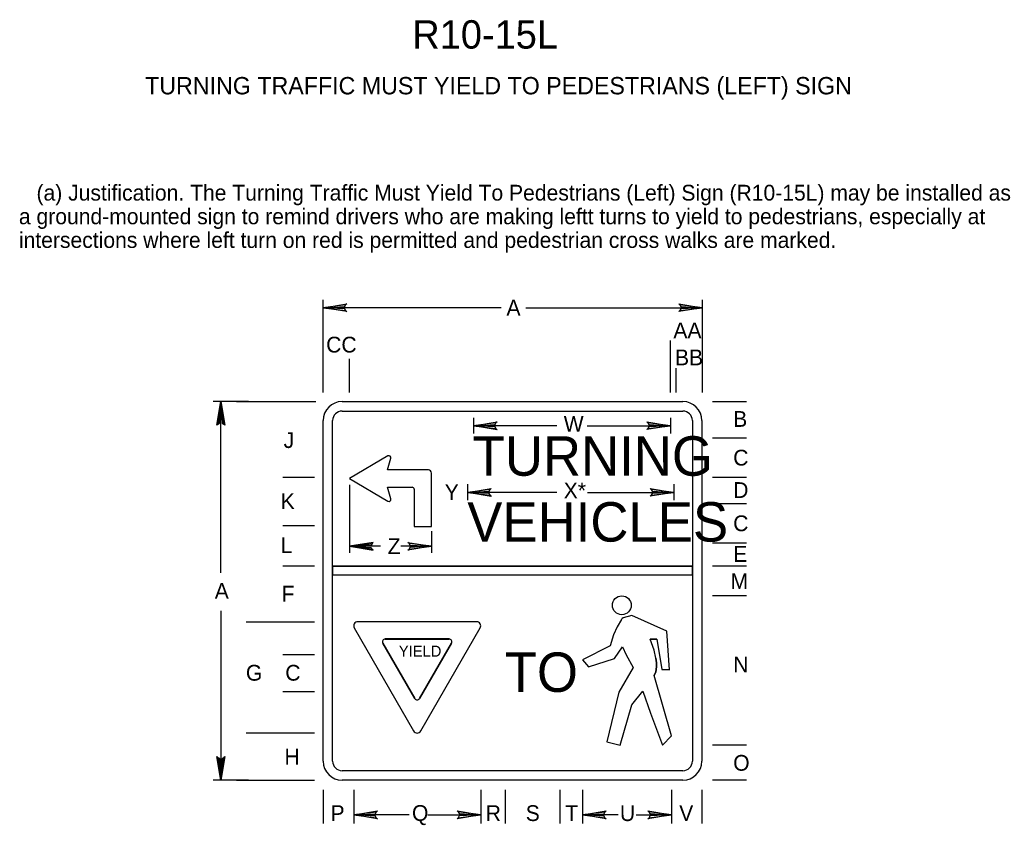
# Model space of a CAD drawing. Extents: x 0.013 to 0.193, y 0.003 to 0.259.
# Drawn here: x 0.0358 to 0.1928, y 0.1316 to 0.2592 of the extents above; entities that cross this region are included whole.
import ezdxf

# ---------------------------------------------------------------- set-up
doc = ezdxf.new("R2010")
doc.units = 0
for name, color, linetype in [('1', 7, 'Continuous'), ('11', 7, 'Continuous'), ('12', 7, 'Continuous'), ('2', 7, 'Continuous'), ('3', 7, 'Continuous')]:
    doc.layers.add(name, color=color, linetype=linetype)

# ---------------------------------------------------------------- blocks, each defined once
blk = doc.blocks.new('RARROW')
at = {"layer": '3'}
for p, q in [((-2.156, 0.28500000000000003), (-2.2665, 0.384625)), ((-2.2665, 0.384625), (0, 0)), ((0, 0), (-2.2665, -0.379125)), ((-2.156, 0.28500000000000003), (-2.075625, 0.12075)), ((0, 0), (-2.156, 0.28500000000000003)), ((-2.14975, -0.2705), (0, 0)), ((-2.075625, 0.12075), (0, 0)), ((0, 0), (-2.074, -0.108)), ((-2.2665, -0.379125), (-2.14975, -0.2705)), ((-2.074, -0.108), (-2.14975, -0.2705))]:
    blk.add_line(p, q, dxfattribs=at)

msp = doc.modelspace()

# ---------------------------------------------------------------- linework, layer by layer
at = {"layer": '11'}
for p, q in [((0.08690494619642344, 0.19868508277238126), (0.14090494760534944, 0.19868508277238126)), ((0.08390494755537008, 0.14168508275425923), (0.08390494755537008, 0.1956850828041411)), ((0.14390494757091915, 0.19568508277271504), (0.1439049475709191, 0.14168508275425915)), ((0.09417475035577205, 0.19007234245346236), (0.08808089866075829, 0.18649377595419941)), ((0.09409819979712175, 0.1878687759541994), (0.09463316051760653, 0.18971593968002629)), ((0.10058089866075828, 0.1878687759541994), (0.09409819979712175, 0.1878687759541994)), ((0.10108089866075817, 0.17886877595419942), (0.10108089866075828, 0.1873687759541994)), ((0.08808089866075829, 0.18649377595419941), (0.094174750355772, 0.18291520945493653)), ((0.09463316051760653, 0.1832716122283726), (0.09409819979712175, 0.1851187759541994)), ((0.09409819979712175, 0.1851187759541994), (0.09801839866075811, 0.1851187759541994)), ((0.09833089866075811, 0.1848062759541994), (0.09833089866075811, 0.17886877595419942)), ((0.09833089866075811, 0.17886877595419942), (0.10108089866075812, 0.17886877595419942)), ((0.14090549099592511, 0.13868508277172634), (0.08690494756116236, 0.13868508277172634))]:
    msp.add_line(p, q, dxfattribs=at)
for centre, radius, start, end in [((0.08690494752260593, 0.1956850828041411), 0.002999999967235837, 90, 180), ((0.14090494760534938, 0.1956850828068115), 0.0029999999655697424, 0, 90), ((0.09433299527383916, 0.18980287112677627), 0.0003125, 343.84835103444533, 120.42325111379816), ((0.10058089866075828, 0.1873687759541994), 0.0005, 1.4210854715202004e-14, 90.00000000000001), ((0.09801839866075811, 0.1848062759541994), 0.0003125, 1.4210854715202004e-14, 90.00000000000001), ((0.09433299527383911, 0.18318468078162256), 0.0003125, 239.57674888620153, 16.151648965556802), ((0.0869049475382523, 0.14168508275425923), 0.0029999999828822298, 180, 270), ((0.14090494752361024, 0.14168508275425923), 0.003000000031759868, 270, 0)]:
    msp.add_arc(centre, radius, start, end, dxfattribs=at)
at = {"layer": '3'}
for p, q in [((0.0839023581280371, 0.20010055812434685), (0.0839023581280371, 0.21482011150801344)), ((0.11208424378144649, 0.21357011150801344), (0.0839023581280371, 0.21357011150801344)), ((0.11600603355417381, 0.21357011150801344), (0.14398465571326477, 0.21357011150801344)), ((0.14398465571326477, 0.20010055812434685), (0.14398465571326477, 0.21482011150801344)), ((0.13893855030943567, 0.20010055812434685), (0.13893855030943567, 0.20838502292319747)), ((0.08808089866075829, 0.20010055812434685), (0.08808089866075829, 0.20547034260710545)), ((0.13985770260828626, 0.20010055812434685), (0.13985770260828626, 0.20395857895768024)), ((0.07208256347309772, 0.19868508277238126), (0.06645704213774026, 0.19868508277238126)), ((0.06707754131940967, 0.19493508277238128), (0.06770704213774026, 0.19868508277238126)), ((0.06770704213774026, 0.19868508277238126), (0.06724059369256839, 0.1951179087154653)), ((0.06750941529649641, 0.19525089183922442), (0.06770704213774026, 0.19868508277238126)), ((0.06770704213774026, 0.19868508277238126), (0.06788380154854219, 0.1952535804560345)), ((0.06814975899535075, 0.19512824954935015), (0.06770704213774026, 0.19868508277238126)), ((0.06770704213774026, 0.19868508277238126), (0.06832754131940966, 0.19493508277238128)), ((0.06770704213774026, 0.1715221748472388), (0.06770704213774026, 0.19868508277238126)), ((0.07018751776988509, 0.19868508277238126), (0.08276001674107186, 0.19868508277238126)), ((0.14561476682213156, 0.19868508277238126), (0.15096409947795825, 0.19868508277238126)), ((0.08690490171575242, 0.19718508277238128), (0.14090494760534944, 0.19718508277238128)), ((0.06724059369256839, 0.1951179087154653), (0.06707754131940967, 0.19493508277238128)), ((0.06724059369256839, 0.1951179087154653), (0.06750941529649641, 0.19525089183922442)), ((0.06788380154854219, 0.1952535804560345), (0.06814975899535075, 0.19512824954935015)), ((0.06832754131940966, 0.19493508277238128), (0.06814975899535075, 0.19512824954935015)), ((0.08540494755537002, 0.14168508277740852), (0.08540494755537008, 0.19568508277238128)), ((0.10771232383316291, 0.19613773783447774), (0.10771232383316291, 0.19361246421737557)), ((0.1107505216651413, 0.19486181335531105), (0.10771232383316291, 0.19486181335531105)), ((0.12092027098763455, 0.19486181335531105), (0.10771232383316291, 0.19486181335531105)), ((0.1257335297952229, 0.19486181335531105), (0.13891866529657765, 0.19486181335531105)), ((0.13891866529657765, 0.19613773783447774), (0.13891866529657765, 0.19361246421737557)), ((0.14240494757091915, 0.19568508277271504), (0.1424049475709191, 0.1416850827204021)), ((0.14561476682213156, 0.1929522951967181), (0.15096409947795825, 0.1929522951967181)), ((0.07750953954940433, 0.1866850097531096), (0.08251195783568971, 0.1866848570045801)), ((0.08808089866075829, 0.18551543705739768), (0.08808089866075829, 0.1747305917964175)), ((0.1067884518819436, 0.18557594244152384), (0.1067884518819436, 0.18305066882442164)), ((0.13945473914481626, 0.18557594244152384), (0.13945473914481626, 0.18305066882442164)), ((0.14561476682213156, 0.18670190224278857), (0.15096409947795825, 0.18670190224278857)), ((0.12092027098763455, 0.18430001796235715), (0.1067884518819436, 0.18430001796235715)), ((0.1107505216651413, 0.18430001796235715), (0.10771232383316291, 0.18430001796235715)), ((0.1257791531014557, 0.18430066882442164), (0.13891866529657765, 0.18430066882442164)), ((0.14561476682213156, 0.18251596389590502), (0.15096409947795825, 0.18251596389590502)), ((0.07750953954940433, 0.17906008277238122), (0.08251195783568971, 0.17906008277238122)), ((0.10108089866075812, 0.17817008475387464), (0.10108089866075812, 0.1747305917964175)), ((0.09296959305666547, 0.17574919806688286), (0.08808219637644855, 0.17574919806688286)), ((0.10108089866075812, 0.17574919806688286), (0.0961935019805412, 0.17574919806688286)), ((0.14561476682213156, 0.17632260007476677), (0.15096409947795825, 0.17632260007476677)), ((0.07750953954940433, 0.1726499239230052), (0.08251195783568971, 0.1726499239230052)), ((0.08540494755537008, 0.1726259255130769), (0.14240494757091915, 0.1726259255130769)), ((0.14561476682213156, 0.1726499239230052), (0.15096409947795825, 0.1726499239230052)), ((0.15096409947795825, 0.1726259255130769), (0.14561476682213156, 0.1726259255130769)), ((0.08540494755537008, 0.1712513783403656), (0.14240494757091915, 0.1712513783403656)), ((0.15096409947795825, 0.16789987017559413), (0.14561476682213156, 0.16789987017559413)), ((0.06770704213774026, 0.1655199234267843), (0.06770704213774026, 0.13868508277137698)), ((0.13279025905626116, 0.16479111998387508), (0.13142307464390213, 0.1644100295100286)), ((0.1383594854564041, 0.16228291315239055), (0.13279025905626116, 0.16479111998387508)), ((0.07173007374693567, 0.1637978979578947), (0.08251195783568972, 0.1637978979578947)), ((0.10821642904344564, 0.16379789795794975), (0.08940375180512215, 0.16379789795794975)), ((0.13114973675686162, 0.16415573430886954), (0.13047708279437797, 0.16300912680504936)), ((0.13114973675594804, 0.16415573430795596), (0.13123330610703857, 0.16423930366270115)), ((0.13142307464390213, 0.1644100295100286), (0.13123330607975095, 0.1642393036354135)), ((0.08883119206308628, 0.16281636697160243), (0.098237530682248, 0.1464847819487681)), ((0.09938265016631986, 0.1464847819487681), (0.10878898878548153, 0.16281636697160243)), ((0.12989589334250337, 0.16173825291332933), (0.1293873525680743, 0.15999533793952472)), ((0.13047708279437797, 0.16300912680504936), (0.12989589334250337, 0.16173825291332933)), ((0.13876994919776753, 0.15619917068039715), (0.1383594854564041, 0.16228291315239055)), ((0.09335714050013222, 0.16041706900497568), (0.09842838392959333, 0.15161055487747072)), ((0.10388133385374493, 0.16107142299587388), (0.09373884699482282, 0.16107142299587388)), ((0.09919179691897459, 0.15161055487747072), (0.10426304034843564, 0.16041706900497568)), ((0.135707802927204, 0.16101203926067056), (0.13679753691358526, 0.16104834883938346)), ((0.13632531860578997, 0.159269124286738), (0.135707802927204, 0.16101203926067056)), ((0.13679753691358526, 0.16104834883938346), (0.13754989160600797, 0.156234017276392)), ((0.08251195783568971, 0.15857694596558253), (0.07750953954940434, 0.15857694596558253)), ((0.1300411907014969, 0.15796193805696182), (0.13134887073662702, 0.1598137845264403)), ((0.13134887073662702, 0.1598137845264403), (0.13189373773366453, 0.15854291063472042)), ((0.13189373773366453, 0.15854291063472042), (0.13301979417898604, 0.15654582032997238)), ((0.13660264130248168, 0.15804162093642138), (0.13632531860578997, 0.159269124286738)), ((0.12597207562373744, 0.15662734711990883), (0.1300411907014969, 0.15796193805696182)), ((0.1366950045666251, 0.15730299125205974), (0.13660264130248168, 0.15804162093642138)), ((0.1367240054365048, 0.15667239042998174), (0.1366950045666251, 0.15730299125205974)), ((0.13301979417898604, 0.15654582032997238), (0.13075244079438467, 0.15264492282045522)), ((0.1363721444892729, 0.15530065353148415), (0.13662724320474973, 0.15584583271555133)), ((0.13662724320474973, 0.15584583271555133), (0.1367240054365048, 0.15667239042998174)), ((0.13754989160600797, 0.156234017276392), (0.13876994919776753, 0.15619917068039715)), ((0.13909332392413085, 0.14572305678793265), (0.1363721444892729, 0.15530065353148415)), ((0.08251195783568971, 0.1526689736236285), (0.07750953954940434, 0.1526689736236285)), ((0.13075244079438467, 0.15264492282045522), (0.12883520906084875, 0.14476982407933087)), ((0.13280910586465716, 0.1506238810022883), (0.13454542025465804, 0.15276950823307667)), ((0.13454542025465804, 0.15276950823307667), (0.13574412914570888, 0.14928367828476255)), ((0.1309615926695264, 0.14421229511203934), (0.13280910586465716, 0.1506238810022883)), ((0.13574412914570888, 0.14928367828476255), (0.13764851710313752, 0.1442605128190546)), ((0.08251195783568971, 0.14615411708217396), (0.07173007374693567, 0.14615411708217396)), ((0.12883520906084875, 0.14476982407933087), (0.1309615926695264, 0.14421229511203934)), ((0.13764851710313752, 0.1442605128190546), (0.13909332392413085, 0.14572305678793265)), ((0.15096409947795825, 0.14421229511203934), (0.14561476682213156, 0.14421229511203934)), ((0.1409053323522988, 0.14018508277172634), (0.08690494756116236, 0.14018508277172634)), ((0.07208256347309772, 0.13868508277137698), (0.06645704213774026, 0.13868508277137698)), ((0.07018751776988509, 0.13868508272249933), (0.08254232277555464, 0.13868508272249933)), ((0.15096409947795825, 0.13868508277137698), (0.14561476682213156, 0.13868508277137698)), ((0.08390494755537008, 0.13715713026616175), (0.08390494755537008, 0.13181920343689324)), ((0.08874861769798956, 0.13715713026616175), (0.08874941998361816, 0.13181920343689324)), ((0.10887500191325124, 0.13715713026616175), (0.1088749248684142, 0.13181920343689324)), ((0.11275340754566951, 0.13715713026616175), (0.11275340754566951, 0.13181920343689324)), ((0.12142183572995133, 0.13715713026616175), (0.12142183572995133, 0.13181920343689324)), ((0.12498914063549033, 0.13715713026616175), (0.12498914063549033, 0.13181920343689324)), ((0.13909332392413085, 0.13715713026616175), (0.13909332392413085, 0.13181920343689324)), ((0.14390494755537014, 0.13715713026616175), (0.14390494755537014, 0.13181920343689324)), ((0.09751237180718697, 0.1331922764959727), (0.08874921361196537, 0.1331922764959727)), ((0.10048717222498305, 0.13318855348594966), (0.10887494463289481, 0.13318855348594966)), ((0.1306475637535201, 0.1331922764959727), (0.12498330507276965, 0.1331922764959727)), ((0.13350308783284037, 0.13318855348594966), (0.13909332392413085, 0.13318855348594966))]:
    msp.add_line(p, q, dxfattribs=at)
for points in [[(0.08540494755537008, 0.1712513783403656), (0.14240494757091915, 0.1712513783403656), (0.14240494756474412, 0.1726259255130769), (0.08540494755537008, 0.1726259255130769), (0.08540494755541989, 0.1712513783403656)], [(0.1082164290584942, 0.16379789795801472), (0.08940375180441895, 0.16379789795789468)], [(0.08883119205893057, 0.16281636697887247), (0.0982375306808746, 0.14648478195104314)], [(0.0993826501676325, 0.14648478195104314), (0.10878898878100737, 0.16281636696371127)], [(0.0984343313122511, 0.15162121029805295), (0.09336331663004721, 0.16040566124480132)], [(0.09374117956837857, 0.16105989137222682), (0.10388370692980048, 0.16105989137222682)], [(0.1042616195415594, 0.16040574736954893), (0.09918966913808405, 0.1516216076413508)], [(0.13679753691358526, 0.16104834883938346), (0.135707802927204, 0.16101203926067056), (0.13679753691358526, 0.16104834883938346)], [(0.1293873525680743, 0.15999533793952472), (0.12498914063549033, 0.15774771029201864), (0.12597207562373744, 0.15662734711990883)], [(0.13660264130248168, 0.15804162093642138), (0.1366950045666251, 0.15730299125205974), (0.1367240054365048, 0.15667239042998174), (0.13662724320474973, 0.15584583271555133), (0.1363721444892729, 0.15530065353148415), (0.13662724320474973, 0.15584583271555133), (0.1367240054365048, 0.15667239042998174), (0.1366950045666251, 0.15730299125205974), (0.13660264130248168, 0.15804162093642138)], [(0.13876994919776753, 0.15619917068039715), (0.13754989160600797, 0.156234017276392), (0.13876994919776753, 0.15619917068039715)]]:
    msp.add_lwpolyline(points, dxfattribs=at)
msp.add_circle((0.13122529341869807, 0.1664039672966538), 0.0014959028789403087, dxfattribs=at)
for centre, radius, start, end in [((0.08690494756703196, 0.19568508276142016), 0.0015000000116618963, 90, 180), ((0.1409049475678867, 0.19568508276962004), 0.001500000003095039, 0, 90), ((0.08940070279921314, 0.16314191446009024), 0.0006559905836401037, 89.73369166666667, 209.75343333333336), ((0.08940070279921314, 0.16314191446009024), 0.0006559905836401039, 89.73369166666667, 209.75343333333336), ((0.10821926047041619, 0.1631417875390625), 0.0006561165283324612, 330.2656166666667, 90.24725555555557), ((0.10821926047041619, 0.1631417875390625), 0.0006561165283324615, 330.2656166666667, 90.24725555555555), ((0.09374117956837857, 0.1606236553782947), 0.0004362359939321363, 90, 209.98121666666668), ((0.09374117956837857, 0.1606236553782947), 0.0004362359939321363, 89.99999999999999, 209.98121666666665), ((0.10388370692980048, 0.1606236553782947), 0.0004362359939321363, 330.03184166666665, 90), ((0.10388370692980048, 0.1606236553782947), 0.0004362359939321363, 330.03184166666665, 89.99999999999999), ((0.09881188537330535, 0.1518397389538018), 0.00043623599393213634, 210.0623, 329.99798055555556), ((0.09881188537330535, 0.1518397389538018), 0.0004362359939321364, 210.06229999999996, 329.9979805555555), ((0.09881009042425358, 0.14681515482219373), 0.0006610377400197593, 209.9853888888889, 330.0146111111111), ((0.09881009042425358, 0.14681515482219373), 0.0006610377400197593, 209.98538888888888, 330.0146111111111), ((0.08690494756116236, 0.14168508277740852), 0.001500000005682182, 180, 270), ((0.14090494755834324, 0.1416850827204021), 0.0014999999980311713, 270, 0)]:
    msp.add_arc(centre, radius, start, end, dxfattribs=at)

# ---------------------------------------------------------------- block references
at = {"layer": '3', "xscale": 0.0016545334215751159}
for p, yscale, rotation in [((0.0839023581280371, 0.21357011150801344), 0.0016366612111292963, 180), ((0.10771232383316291, 0.19486181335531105), 0.0016366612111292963, 180), ((0.1067884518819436, 0.18430001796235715), 0.0016366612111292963, 180), ((0.08808219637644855, 0.17574919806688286), -0.0016366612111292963, 180), ((0.06770704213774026, 0.13868508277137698), 0.0016366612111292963, -90), ((0.08874921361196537, 0.1331922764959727), 0.0016366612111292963, 180), ((0.12498330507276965, 0.1331922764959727), 0.0016366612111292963, 180)]:
    msp.add_blockref('RARROW', p, dxfattribs=dict(at, yscale=yscale, rotation=rotation))
at = {"layer": '3', "xscale": 0.0016545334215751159, "yscale": 0.0016366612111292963}
for p in [(0.14398465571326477, 0.21357011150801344), (0.1389186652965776, 0.194861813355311), (0.13945473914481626, 0.18430066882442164), (0.10108089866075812, 0.17574919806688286), (0.10887494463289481, 0.13318855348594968), (0.13909332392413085, 0.13318855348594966)]:
    msp.add_blockref('RARROW', p, dxfattribs=at)

# ---------------------------------------------------------------- texts
at = {"layer": '1'}
for s, height, p in [('R10-15L', 0.0045000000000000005, (0.09802772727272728, 0.254625)), ('TURNING TRAFFIC MUST YIELD TO PEDESTRIANS (LEFT) SIGN', 0.00275025, (0.055704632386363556, 0.247375))]:
    msp.add_text(s, height=height, dxfattribs=at).set_placement(p)
at = {"layer": '12'}
for s, p in [('TURNING', (0.10758950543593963, 0.18693790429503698)), ('VEHICLES', (0.106734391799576, 0.17649524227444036)), ('TO', (0.11267443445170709, 0.15267754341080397))]:
    msp.add_text(s, height=0.0062499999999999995, dxfattribs=at).set_placement(p)
at = {"layer": '2'}
for s, p in [('   (a) Justification. The Turning Traffic Must Yield To Pedestrians (Left) Sign (R10-15L) may be installed as ', (0.035703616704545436, 0.23054097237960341)), ('a ground-mounted sign to remind drivers who are making leftt turns to yield to pedestrians, especially at ', (0.035703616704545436, 0.2267912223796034)), ('intersections where left turn on red is permitted and pedestrian cross walks are marked.', (0.035703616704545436, 0.22304147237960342))]:
    msp.add_text(s, height=0.0024997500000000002, dxfattribs=at).set_placement(p)
at = {"layer": '3'}
for s, height, p in [('A', 0.0025, (0.11294888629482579, 0.21232011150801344)), ('AA', 0.0025, (0.13939172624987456, 0.20871156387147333)), ('CC', 0.0025, (0.08438267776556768, 0.20646205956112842)), ('BB', 0.0025, (0.13965081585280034, 0.20443629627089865)), ('W', 0.0024997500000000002, (0.1220233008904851, 0.1939133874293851)), ('B', 0.0024997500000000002, (0.14887224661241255, 0.19468508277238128)), ('J', 0.0024997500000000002, (0.07764453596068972, 0.19133097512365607)), ('C', 0.0024997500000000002, (0.14887224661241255, 0.18854874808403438)), ('Y', 0.0024997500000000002, (0.10316426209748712, 0.18309170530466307)), ('X*', 0.0024997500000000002, (0.1220233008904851, 0.1833515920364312)), ('D', 0.0024997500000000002, (0.14887224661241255, 0.18341702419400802)), ('K', 0.0024997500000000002, (0.07719018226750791, 0.18164931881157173)), ('C', 0.0024997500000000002, (0.14887224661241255, 0.17814753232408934)), ('L', 0.0024997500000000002, (0.0771901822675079, 0.1746801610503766)), ('Z', 0.0024997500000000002, (0.09411761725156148, 0.17451122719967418)), ('E', 0.0024997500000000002, (0.14887224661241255, 0.17328865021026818)), ('M', 0.0024997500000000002, (0.14846104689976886, 0.16897882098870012)), ('A', 0.0024997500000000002, (0.06672871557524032, 0.1674352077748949)), ('F', 0.0024997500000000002, (0.07730974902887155, 0.16699444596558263)), ('YIELD', 0.001744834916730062, (0.09589276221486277, 0.15826315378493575)), ('G', 0.0024997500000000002, (0.07166702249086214, 0.1544602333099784)), ('C', 0.0024997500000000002, (0.07790758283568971, 0.1544602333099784)), ('N', 0.0024997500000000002, (0.14887224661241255, 0.15577711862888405)), ('H', 0.0024997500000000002, (0.07777692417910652, 0.14116418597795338)), ('O', 0.0024997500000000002, (0.14887224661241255, 0.14018400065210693)), ('P', 0.0024997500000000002, (0.08507033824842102, 0.13221533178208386)), ('Q', 0.0024997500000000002, (0.0979823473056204, 0.13223947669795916)), ('R', 0.0024997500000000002, (0.10966130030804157, 0.13221533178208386)), ('S', 0.0024997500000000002, (0.11600293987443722, 0.13221533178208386)), ('T', 0.0024997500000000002, (0.12225214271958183, 0.13221533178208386)), ('U', 0.0024997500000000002, (0.13092176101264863, 0.13221533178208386)), ('V', 0.0024997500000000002, (0.14032016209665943, 0.13221533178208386))]:
    msp.add_text(s, height=height, dxfattribs=at).set_placement(p)

doc.saveas('drawing.dxf')
